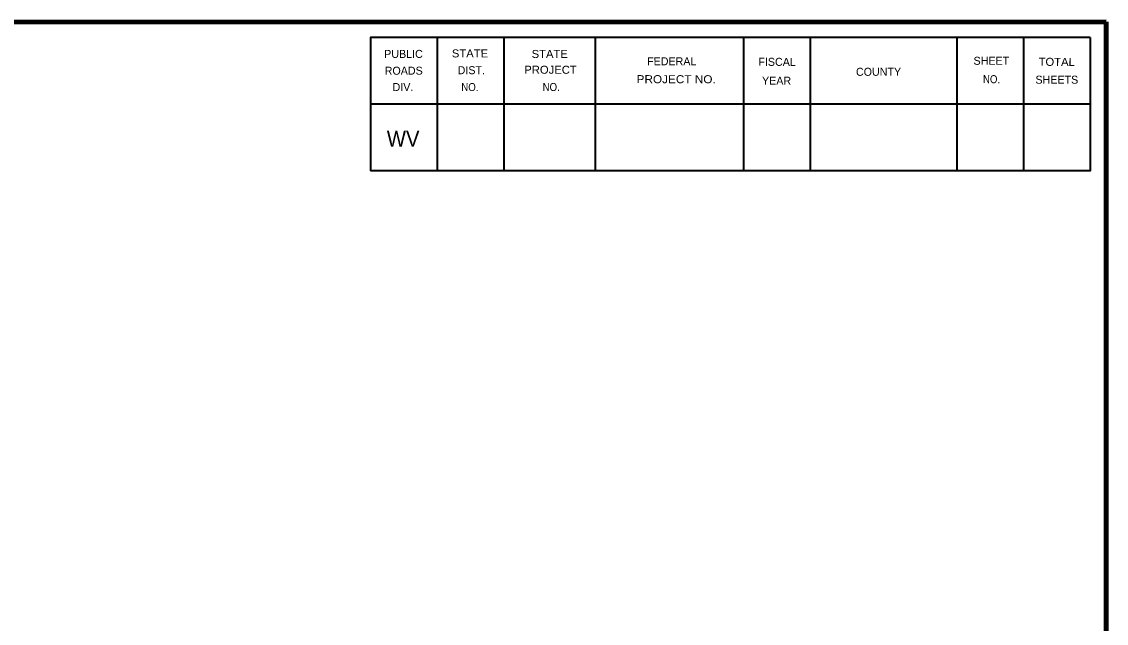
# Model space of a CAD drawing. Extents: x -50 to 806, y -9 to 535.
# Drawn here: x 592.5 to 799.2, y 414.3 to 528.9 of the extents above; entities that cross this region are included whole.
import ezdxf

# ---------------------------------------------------------------- set-up
doc = ezdxf.new("R2010")
doc.units = 0
doc.header["$LTSCALE"] = 1.2
doc.layers.add('1', color=7, linetype='Continuous', lineweight=35)
doc.layers.add('61', color=7, linetype='Continuous', lineweight=35)

msp = doc.modelspace()

# ---------------------------------------------------------------- linework, layer by layer
at = {"layer": '1', "lineweight": 158}
msp.add_line((799.155, 2.763), (799.155, 528.863), dxfattribs=at)
at = {"layer": '1', "lineweight": 13}
msp.add_line((799.155, 2.763), (799.155, 528.863), dxfattribs=at)
at = {"layer": '1', "lineweight": 158}
msp.add_lwpolyline([(799.155, 528.863), (7.455, 528.763), (7.555, 2.763)], dxfattribs=at)
at = {"layer": '61'}
for p, q in [((671.655, 525.863), (671.655, 500.463)), ((684.355, 525.863), (684.355, 500.463)), ((701.755, 525.863), (701.755, 500.463)), ((730.055, 525.863), (730.055, 500.463)), ((742.755, 525.863), (742.755, 500.463)), ((770.655, 525.863), (770.655, 500.463)), ((783.355, 525.863), (783.355, 500.463)), ((796.055, 513.163), (658.955, 513.163))]:
    msp.add_line(p, q, dxfattribs=at)
for points in [[(796.055, 525.863), (658.955, 525.863), (658.955, 500.463)], [(796.055, 525.863), (796.055, 500.463), (658.955, 500.463)]]:
    msp.add_lwpolyline(points, dxfattribs=at)

# ---------------------------------------------------------------- texts
at = {"layer": '1', "width": 0.95}
msp.add_text('WV', height=3.048, dxfattribs=at).set_placement((662.055, 505.063))
at = {"layer": '61'}
for s, height, rotation, p in [('PUBLIC', 1.525, 0.033, (661.555, 521.963)), ('FEDERAL', 1.523, 0.007, (711.655, 520.563)), ('FISCAL', 1.525, 359.942, (732.855, 520.463)), ('SHEET', 1.525, 0.059, (773.855, 520.663)), ('ROADS', 1.525, 0.124, (661.655, 518.763)), ('DIST.', 1.525, 0.056, (675.555, 518.863)), ('COUNTY', 1.523, 0.069, (751.455, 518.563)), ('DIV.', 1.525, 359.932, (663.155, 515.663)), ('YEAR', 1.523, 0.105, (733.555, 516.863)), ('SHEETS', 1.523, 359.959, (785.655, 517.063))]:
    msp.add_text(s, height=height, rotation=rotation, dxfattribs=at).set_placement(p)
for s, rotation, width, p in [('STATE', 0.059, 1.05, (674.455, 522.063)), ('STATE', 0.059, 1.05, (689.655, 521.963)), ('TOTAL', 359.926, 1.05, (786.255, 520.463)), ('PROJECT', 359.908, 1.05, (688.255, 518.963)), ('NO.', 359.852, 0.9, (676.255, 515.663)), ('NO.', 0.225, 0.9, (691.755, 515.663)), ('PROJECT NO.', 359.922, 1.1, (709.655, 517.163)), ('NO.', 359.852, 0.9, (775.655, 517.163))]:
    msp.add_text(s, height=1.525, rotation=rotation, dxfattribs=dict(at, width=width)).set_placement(p)

doc.saveas('drawing.dxf')
